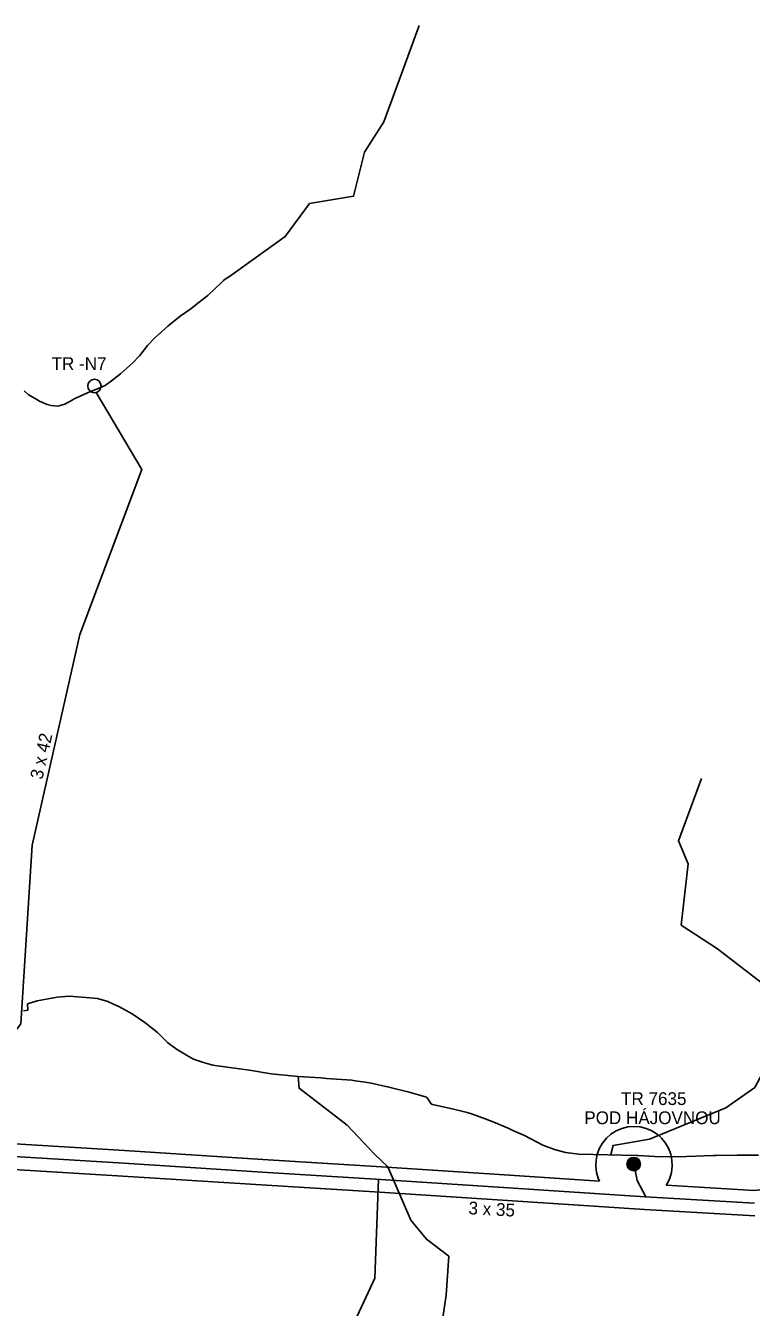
# Model space of a CAD drawing. Extents: x -439095 to -431527, y -1129525 to -1119219.
# Drawn here: x -437185 to -436616, y -1124404 to -1123399 of the extents above; entities that cross this region are included whole.
import ezdxf

# ---------------------------------------------------------------- set-up
doc = ezdxf.new("R2010")
doc.units = 0
for name, color, linetype in [('Hranice reseneho uzemi', 7, 'Continuous'), ('UZEMNI REZERVA', 7, 'Continuous'), ('Vrstva 11', 7, 'Continuous'), ('Vrstva 13', 7, 'Continuous'), ('Vrstva 19', 7, 'Continuous'), ('Vrstva 21', 7, 'Continuous'), ('ZU', 7, 'Continuous')]:
    doc.layers.add(name, color=color, linetype=linetype)

msp = doc.modelspace()

# ---------------------------------------------------------------- linework, layer by layer
at = {"layer": 'Hranice reseneho uzemi'}
for points in [[(-437129.4, -1123686.5), (-437093.8, -1123746.9), (-437142.4, -1123876.3), (-437179.6, -1124041.5), (-437188.5, -1124181.5), (-437266.5, -1124282.1)], [(-437197.9, -1124285.4), (-437107.9, -1124290.9), (-436999.5, -1124297.8), (-436906.4, -1124303.5), (-436806.3, -1124310.2), (-436699.2, -1124317.2), (-436613.5, -1124322.2)], [(-436698.7, -1124317.2), (-436705.4, -1124304.3), (-436707.9, -1124292)], [(-436908.2, -1124303.4), (-436911.1, -1124380.9), (-437003.6, -1124579.9)]]:
    msp.add_lwpolyline(points, dxfattribs=at)
at = {"layer": 'UZEMNI REZERVA'}
for points in [[(-437025.1, -1123595.7), (-436981.3, -1123564.2), (-436962.2, -1123538.4), (-436927.9, -1123532.7), (-436919.3, -1123498.3), (-436904, -1123474.4), (-436890.2, -1123436.7), (-436876.3, -1123399)], [(-437186, -1123685.4), (-437182.7, -1123688.1), (-437180.9, -1123689.3), (-437176, -1123692.2), (-437174, -1123693.4), (-437168, -1123695.9), (-437164.8, -1123696.8), (-437159.7, -1123697.4), (-437154.1, -1123695.7), (-437148.3, -1123692.6), (-437146.7, -1123691.7), (-437136.4, -1123687), (-437127.9, -1123683.6), (-437122.5, -1123681.2), (-437117.5, -1123677.4), (-437110.4, -1123672.1), (-437100.8, -1123663.3), (-437096, -1123658.3), (-437095.3, -1123657.6), (-437089.2, -1123649.7), (-437083.2, -1123643.4), (-437073.3, -1123634.6), (-437063.7, -1123626.8), (-437055.4, -1123621), (-437049.8, -1123616.5), (-437042, -1123610.5), (-437036, -1123604.9), (-437032.2, -1123601.1), (-437029.8, -1123598.7), (-437028.3, -1123597.8), (-437026.3, -1123596.5), (-437025.1, -1123595.7)], [(-436726.1, -1124283.9), (-436724.3, -1124276.9), (-436695.8, -1124271.9), (-436635.9, -1124247.3), (-436613.3, -1124231.5), (-436598.6, -1124204.1), (-436595.7, -1124158.9), (-436642.5, -1124122.7), (-436670.9, -1124104.1), (-436665.5, -1124056.1), (-436673.1, -1124038.1), (-436655, -1123989.1)], [(-437186.4, -1124171.5), (-437183.1, -1124170.9), (-437183, -1124170.6), (-437183.3, -1124166.1), (-437183.3, -1124165.9), (-437175.7, -1124163.6), (-437164.4, -1124161.4), (-437160, -1124160.6), (-437150.6, -1124159.9), (-437137.5, -1124160.8), (-437128.5, -1124161.6), (-437120.3, -1124164.1), (-437115.9, -1124166.1), (-437111.8, -1124167.9), (-437101.4, -1124173.7), (-437091.4, -1124180.6), (-437081.4, -1124188.4), (-437078.6, -1124191.2), (-437073.5, -1124196.2), (-437066.5, -1124201.3), (-437058.7, -1124206.2), (-437055, -1124208.2), (-437053.2, -1124209.2), (-437045.5, -1124212), (-437038.1, -1124214), (-437025.1, -1124215.9), (-437009.4, -1124217.8), (-436992.4, -1124220.7), (-436992.3, -1124220.8), (-436971.1, -1124222.8), (-436953.3, -1124224), (-436951.4, -1124224.1), (-436948.9, -1124224.3), (-436929.2, -1124225.7), (-436926.4, -1124226.2), (-436918.8, -1124227.3), (-436914.1, -1124228), (-436900.1, -1124231.2), (-436884.2, -1124235.1), (-436875, -1124237.8), (-436872.3, -1124238.6), (-436870.7, -1124239), (-436870.3, -1124239.5), (-436870.1, -1124239.6), (-436867, -1124244.2), (-436866.7, -1124244.5), (-436865.9, -1124244.9), (-436850.5, -1124248.2), (-436841.9, -1124250.3), (-436838.6, -1124251.1), (-436834.5, -1124252.5), (-436829.5, -1124254.3), (-436824.7, -1124256.1), (-436817.7, -1124258.6), (-436806.5, -1124263.4), (-436802.8, -1124265.1), (-436793.7, -1124269.2), (-436779.4, -1124276.7), (-436770.4, -1124280.2), (-436761.6, -1124282.5), (-436751.2, -1124283.8), (-436728.4, -1124284.3), (-436705.8, -1124284.8), (-436704.8, -1124284.8), (-436691.6, -1124285.5), (-436680.4, -1124285.9), (-436666.9, -1124285.6), (-436646, -1124284.9), (-436643.7, -1124284.8), (-436643.3, -1124284.8), (-436627.1, -1124284.4), (-436610.3, -1124284.5)], [(-436971.1, -1124222.8), (-436970.5, -1124232), (-436932.9, -1124261), (-436911.4, -1124283.8), (-436900.9, -1124293.7), (-436883, -1124335.6), (-436870.7, -1124350.4), (-436853.2, -1124363.8), (-436855.2, -1124394.3), (-436860.8, -1124431.4)]]:
    msp.add_lwpolyline(points, dxfattribs=at)
at = {"layer": 'Vrstva 11'}
for radius in [5.25, 4.55, 3.85, 3.15, 2.45, 1.75, 1.05, 0.35]:
    msp.add_circle((-436708.2, -1124291.5), radius, dxfattribs=at)
at = {"layer": 'Vrstva 19'}
msp.add_circle((-437130.9, -1123681.5), 5.25, dxfattribs=at)
at = {"layer": 'ZU'}
for points in [[(-437793.3, -1124030.5), (-437769.7, -1124059.8), (-437717.4, -1124126.6), (-437648.4, -1124212.8), (-437589.1, -1124285.1), (-437554.1, -1124286.6), (-437507.9, -1124287.4), (-437408.6, -1124287.3), (-437307.5, -1124270.1), (-437197.4, -1124275.4), (-437107.2, -1124280.9), (-436998.9, -1124287.8), (-436905.8, -1124293.6), (-436805.6, -1124300.2), (-436735, -1124304.8)], [(-436682.7, -1124308.1), (-436613.8, -1124312.2), (-436538.1, -1124303.4), (-436456.4, -1124294.8), (-436388.8, -1124252.3), (-436310.5, -1124202.8), (-436202.1, -1124212.6), (-436123.9, -1124208.6), (-436042.2, -1124203.6), (-435968.1, -1124183.1), (-435885.5, -1124172.4), (-435784.3, -1124160.8), (-435726.6, -1124174.7), (-435726.6, -1124174.7), (-435716.7, -1124177.1)], [(-436735, -1124304.8), (-436736, -1124302.6), (-436737.3, -1124298), (-436737.9, -1124293.2), (-436737.7, -1124288.4), (-436736.7, -1124283.7), (-436735, -1124279.1), (-436732.6, -1124275), (-436729.6, -1124271.2), (-436726, -1124268), (-436721.9, -1124265.4), (-436717.4, -1124263.5), (-436712.7, -1124262.4), (-436707.9, -1124262), (-436703.1, -1124262.4), (-436698.4, -1124263.5), (-436694, -1124265.4), (-436689.9, -1124268), (-436686.3, -1124271.2), (-436683.2, -1124275), (-436680.8, -1124279.1), (-436679.1, -1124283.7), (-436678.2, -1124288.4), (-436678, -1124293.2), (-436678.5, -1124298), (-436679.9, -1124302.6), (-436682, -1124307), (-436682.7, -1124308.1)], [(-436613.2, -1124332.2), (-436699.8, -1124327.2), (-436807, -1124320.1), (-436907.1, -1124313.5), (-437000.2, -1124307.8), (-437108.5, -1124300.9), (-437198.4, -1124295.4), (-437306.3, -1124290.2), (-437406.9, -1124307.3), (-437508, -1124307.4), (-437554.5, -1124306.6), (-437554.6, -1124306.6), (-437580.4, -1124305.5)]]:
    msp.add_lwpolyline(points, dxfattribs=at)

# ---------------------------------------------------------------- texts
at = {"layer": 'Vrstva 13'}
for s, rotation, p in [('3 x 42', 77.4278, (-437171.7, -1123990.5)), ('3 x 35', 356.971, (-436837.9, -1124330.8))]:
    msp.add_text(s, height=10, rotation=rotation, dxfattribs=at).set_placement(p)
for s, p in [('TR 7635', (-436718.1, -1124245.2)), ('POD HÁJOVNOU', (-436746.9, -1124260.2))]:
    msp.add_text(s, height=10, dxfattribs=at).set_placement(p)
at = {"layer": 'Vrstva 21'}
msp.add_text('TR -N7', height=10, dxfattribs=at).set_placement((-437164.5, -1123669))

doc.saveas('drawing.dxf')
